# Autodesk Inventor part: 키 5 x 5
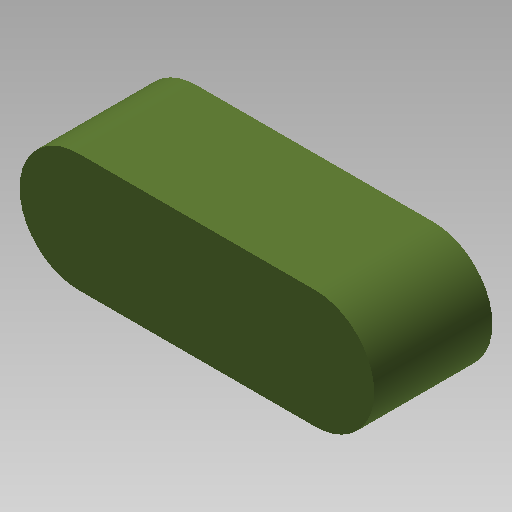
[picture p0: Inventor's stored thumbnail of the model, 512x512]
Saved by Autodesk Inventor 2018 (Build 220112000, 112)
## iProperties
Created: 2011-04
Part Number: 키 5 x 5
Document SubType Name: Modeling
Designer: pww
Density: 7.86 g/cm^3
Material: 강철, 연강
Appearance: 올리브 녹색
Author: pww
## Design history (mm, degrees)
sketch "스케치1"
  geometry: L1 (-5, -2.5)-(5, -2.5); L2 (5, 2.5)-(-5, 2.5); A1 r 2.5 centre (-5, 0) between (-5, 2.5) and (-5, -2.5); A2 r 2.5 centre (5, 0) between (5, -2.5) and (5, 2.5); 1 further point
  constraints: 4 end point, 4 point on circle, 2 centre point
extrude "돌출1" new body sketch "스케치1" distance "d0" = 5; taper "d1" = 0 deg
node "솔리드1"
